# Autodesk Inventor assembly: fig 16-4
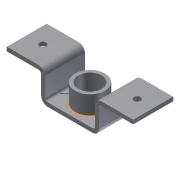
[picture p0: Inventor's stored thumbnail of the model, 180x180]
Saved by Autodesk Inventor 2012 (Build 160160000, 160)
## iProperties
Created: 2004-07
Part Number: fig 16-4
Document SubType Name: Weldment
Designer: CADCIM Technologies
Manufacturer: Standard
Standards Organization: Custom
Author: CADCIM Technologies
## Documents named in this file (3)
- C:\Users\CadCim\Documents\SAILESH\inventor-2011-fact-prt\c16-inv-2011-prt\c16_inv_2012_prt\fig 16-4.iam
- C:\Users\CadCim\Documents\SAILESH\inventor-2011-fact-prt\c16-inv-2011-prt\Bracket.ipt
- C:\Users\CadCim\Documents\SAILESH\inventor-2011-fact-prt\c16-inv-2011-prt\cylinder.ipt
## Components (2 placed, 2 different names)
1. Bracket:1 — Insert:1
2. cylinder:1 — Insert:1
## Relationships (1: Insert 1)
- Insert:1: Bracket:1 ↔ cylinder:1
